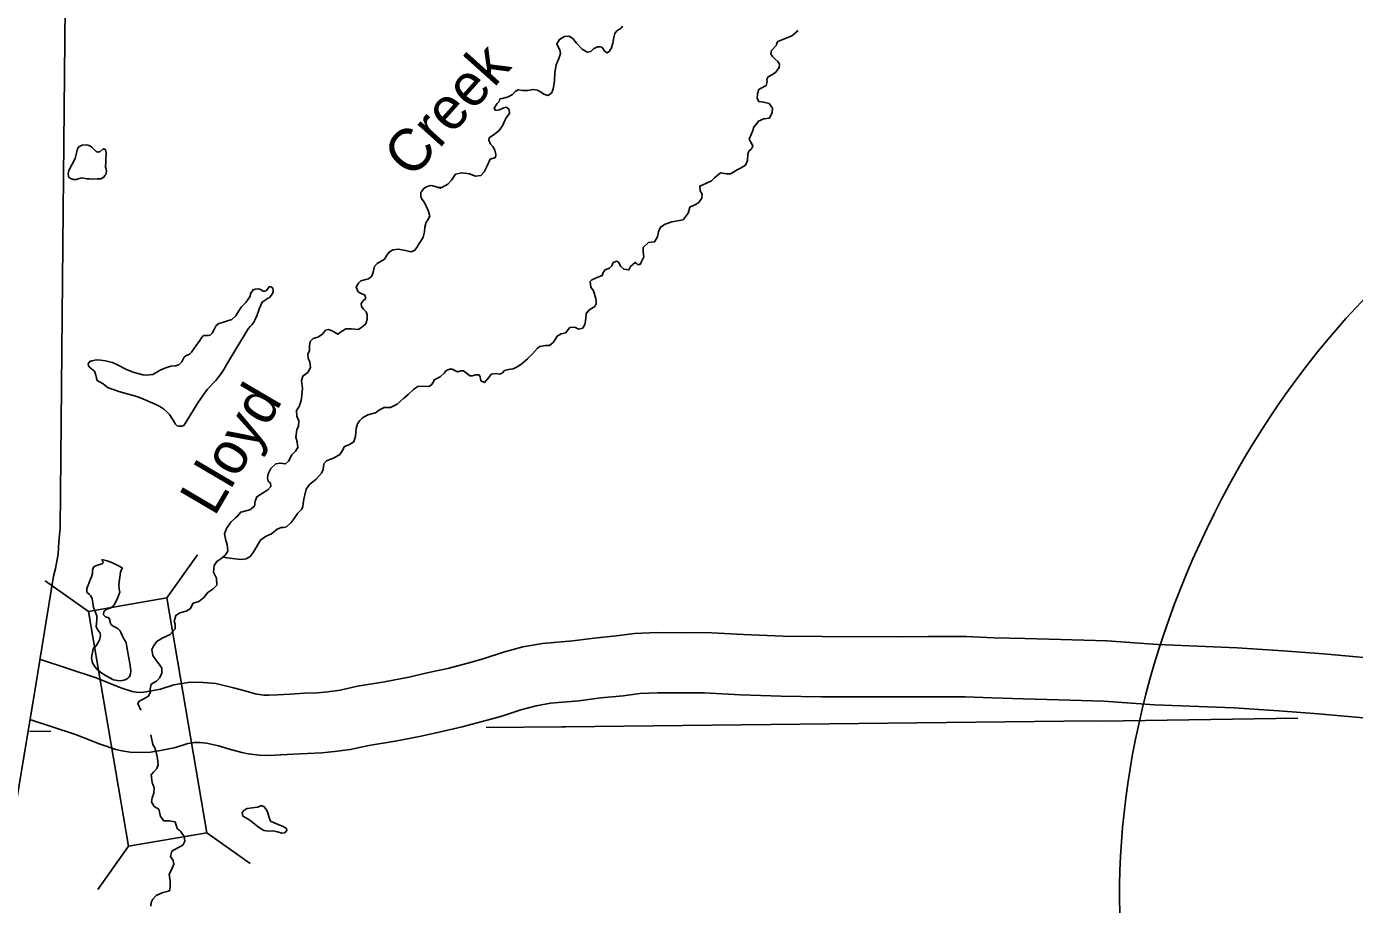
# Model space of a CAD drawing. Extents: x -492261 to -432772, y 1441225 to 1452922.
# Drawn here: x -459788.7 to -459623.3, y 1451872.8 to 1451982.1 of the extents above; entities that cross this region are included whole.
import ezdxf

# ---------------------------------------------------------------- set-up
doc = ezdxf.new("R2010")
doc.units = 0
doc.layers.add('Default', color=7, linetype='Continuous')

msp = doc.modelspace()

# ---------------------------------------------------------------- linework, layer by layer
at = {"layer": 'Default'}
for p, q in [((-459771.2, 1451910.95), (-459767.38, 1451916.33)), ((-459780.96, 1451909.28), (-459786.35, 1451913.1)), ((-459766.22, 1451881.67), (-459760.83, 1451877.85)), ((-459775.98, 1451880.01), (-459779.79, 1451874.62))]:
    msp.add_line(p, q, dxfattribs=at)
for points in [[(-459804.54, 1451796.57), (-459800.12, 1451821.52), (-459795.32, 1451850.99), (-459791.68, 1451875.13), (-459787.55, 1451899.87), (-459785.29, 1451913.65), (-459785.04, 1451914.61), (-459784.72, 1451916.42), (-459784.64, 1451917.99), (-459784.48, 1451919.61), (-459784.15, 1451954.89), (-459783.82, 1451988.91), (-459783.49, 1452028.77), (-459783.44, 1452070.65), (-459782.91, 1452098.16), (-459782.87, 1452118.13)], [(-459714.44, 1451982.2), (-459714.6, 1451981.92), (-459715.13, 1451981.59), (-459715.38, 1451981.28), (-459715.51, 1451980.78), (-459715.64, 1451980.08), (-459715.81, 1451979.5), (-459716.03, 1451979.08), (-459716.35, 1451978.85), (-459716.68, 1451979.07), (-459716.85, 1451979.36), (-459717, 1451979.56), (-459717.22, 1451979.61), (-459717.53, 1451979.59), (-459718.06, 1451979.36), (-459718.36, 1451979.03), (-459718.83, 1451978.93), (-459719.45, 1451979.32), (-459720.14, 1451980.07), (-459720.61, 1451980.63), (-459721.09, 1451980.93), (-459721.65, 1451980.9), (-459722.29, 1451980.53), (-459722.59, 1451979.99), (-459722.45, 1451979.6), (-459722.24, 1451979.24), (-459722.14, 1451978.77), (-459722.38, 1451978.17), (-459722.71, 1451977.37), (-459722.84, 1451976.42), (-459722.91, 1451975.37), (-459723.06, 1451974.33), (-459723.29, 1451973.85), (-459723.72, 1451973.55), (-459724.23, 1451973.7), (-459724.55, 1451973.97), (-459725.01, 1451974.19), (-459725.56, 1451974.31), (-459726.26, 1451974.16), (-459726.9, 1451974.17), (-459727.44, 1451974.23), (-459727.82, 1451974.05), (-459728.13, 1451973.68), (-459728.68, 1451973.36), (-459729.38, 1451973.17), (-459729.69, 1451973.14), (-459729.78, 1451972.81), (-459730.06, 1451972.55), (-459730.41, 1451971.98), (-459730.23, 1451971.69), (-459729.74, 1451971.77), (-459729.22, 1451972.02), (-459728.9, 1451972.08), (-459728.55, 1451971.78), (-459728.49, 1451971.32), (-459728.94, 1451970.75), (-459729.13, 1451970.33), (-459729.36, 1451969.77), (-459729.8, 1451969.18), (-459730.39, 1451968.72), (-459731.02, 1451968.29), (-459731.1, 1451967.98), (-459730.87, 1451967.5), (-459730.6, 1451967.2), (-459730.34, 1451966.72), (-459730.21, 1451966.2), (-459730.26, 1451965.8), (-459730.93, 1451965.6), (-459731.29, 1451964.8), (-459731.66, 1451964.04), (-459732.08, 1451963.57), (-459732.73, 1451963.5), (-459733.5, 1451963.78), (-459734.43, 1451963.89), (-459735.22, 1451963.73), (-459735.72, 1451963.01), (-459736.19, 1451962.5), (-459736.95, 1451962.08), (-459737.49, 1451962.1), (-459737.1, 1451962.01), (-459738.07, 1451962.28), (-459738.33, 1451962.32), (-459738.63, 1451962.26), (-459738.93, 1451962.12), (-459739.2, 1451961.9), (-459739.43, 1451961.63), (-459739.56, 1451961.5), (-459739.56, 1451960.9), (-459739.4, 1451960.59), (-459739.22, 1451960.37), (-459739.01, 1451960.03), (-459738.71, 1451959.39), (-459738.67, 1451959.35), (-459738.45, 1451958.55), (-459738.65, 1451958.1), (-459738.87, 1451957.78), (-459739.04, 1451957.16), (-459739.11, 1451956.54), (-459739.27, 1451955.91)], [(-459692.56, 1451981.65), (-459693.32, 1451980.99), (-459694.46, 1451980.52), (-459695.09, 1451980.28), (-459695.19, 1451980.08), (-459695.26, 1451979.8), (-459695.86, 1451979.16), (-459695.97, 1451978.73), (-459695.75, 1451978.42), (-459695.45, 1451978.13), (-459695.07, 1451977.78), (-459694.89, 1451977.46), (-459694.92, 1451977.02), (-459695.33, 1451976.45), (-459695.75, 1451976.15), (-459696.3, 1451975.88), (-459696.46, 1451975.55), (-459696.41, 1451975.28), (-459696.52, 1451974.79), (-459697.06, 1451974.51), (-459697.44, 1451974.31), (-459697.61, 1451973.76), (-459697.66, 1451973.17), (-459697.46, 1451972.78), (-459696.86, 1451972.73), (-459696.14, 1451972.53), (-459695.76, 1451971.96), (-459695.77, 1451971.41), (-459696.13, 1451970.7), (-459696.84, 1451970.63), (-459697.49, 1451970.36), (-459697.68, 1451970.05), (-459698.06, 1451969.58), (-459698.18, 1451969.19), (-459698.35, 1451968.76), (-459698.66, 1451968.12), (-459698.58, 1451967.92), (-459698.38, 1451967.62), (-459698.18, 1451967.24), (-459698.37, 1451966.89), (-459698.71, 1451966.6), (-459698.81, 1451966.23), (-459698.85, 1451965.46), (-459699.11, 1451964.85), (-459699.73, 1451964.48), (-459700.13, 1451964.27), (-459700.97, 1451963.78), (-459701.46, 1451963.78), (-459702.24, 1451963.89), (-459702.95, 1451963.29), (-459703.33, 1451962.91), (-459704.03, 1451962.57), (-459704.8, 1451962.23), (-459704.77, 1451961.67), (-459704.5, 1451961.27), (-459704.54, 1451960.76), (-459704.97, 1451960.16), (-459705.42, 1451959.94), (-459706.06, 1451959.63), (-459706.27, 1451958.89), (-459706.88, 1451958.05), (-459707.57, 1451957.95), (-459708.29, 1451957.82), (-459709.12, 1451957.51), (-459709.7, 1451957.16), (-459709.94, 1451956.55), (-459710.08, 1451955.95), (-459710.44, 1451955.31), (-459711.2, 1451955.22), (-459711.87, 1451954.6), (-459711.84, 1451954.07), (-459711.78, 1451953.46), (-459712.07, 1451952.85), (-459712.25, 1451952.48), (-459712.57, 1451952.5), (-459712.69, 1451952.62), (-459712.85, 1451952.74), (-459713.43, 1451952.24), (-459713.63, 1451951.81), (-459714.28, 1451951.9), (-459714.68, 1451952.29), (-459714.87, 1451952.73), (-459715.12, 1451952.89), (-459715.58, 1451952.72), (-459715.76, 1451952.31), (-459716.04, 1451952.04), (-459716.6, 1451951.82), (-459716.84, 1451951.49), (-459716.97, 1451951.12), (-459717.5, 1451950.9), (-459718.24, 1451950.6), (-459718.47, 1451950.36), (-459718.36, 1451949.68), (-459718.06, 1451949.2), (-459717.74, 1451948.2), (-459717.7, 1451948.05), (-459717.71, 1451947.57), (-459717.87, 1451947.27), (-459718.63, 1451946.8), (-459718.96, 1451946.33)], [(-459778.87, 1451966.8), (-459778.91, 1451966.84), (-459778.96, 1451966.87), (-459779.04, 1451966.89), (-459779.11, 1451966.89), (-459779.5, 1451966.57), (-459779.75, 1451966.5), (-459780, 1451966.57), (-459780.27, 1451966.84), (-459780.54, 1451967.09), (-459780.7, 1451967.23), (-459781.03, 1451967.37), (-459781.3, 1451967.41), (-459781.74, 1451967.34), (-459782.15, 1451967.13), (-459782.34, 1451966.89), (-459782.45, 1451966.36), (-459782.63, 1451965.69), (-459783.42, 1451964.21), (-459783.48, 1451963.81), (-459783.43, 1451963.43), (-459783.2, 1451963.21), (-459782.82, 1451963.06), (-459782.44, 1451963.08), (-459782.12, 1451963.22), (-459781.8, 1451963.29), (-459781.14, 1451963.18), (-459780.81, 1451963.15), (-459780.42, 1451963.12), (-459779.85, 1451963.15), (-459779.42, 1451963.18), (-459779.06, 1451963.39), (-459778.9, 1451963.58), (-459778.81, 1451963.69), (-459778.75, 1451963.85), (-459778.69, 1451964.1), (-459778.76, 1451964.38), (-459778.82, 1451964.63), (-459778.83, 1451964.79), (-459778.78, 1451965.16), (-459778.79, 1451965.47), (-459778.76, 1451966.37), (-459778.77, 1451966.66), (-459778.82, 1451966.74), (-459778.87, 1451966.8)], [(-459739.27, 1451955.91), (-459739.52, 1451955.48), (-459739.75, 1451955.1), (-459740.04, 1451954.6), (-459740.33, 1451954.25), (-459740.78, 1451954.08), (-459741.47, 1451954.25), (-459742.35, 1451954.41), (-459742.98, 1451954.33), (-459743.47, 1451954.08), (-459743.79, 1451953.67), (-459744.08, 1451953.17), (-459744.56, 1451952.87), (-459745.01, 1451952.62), (-459745.32, 1451952.24), (-459745.5, 1451951.53), (-459745.67, 1451951.02), (-459746.06, 1451950.69), (-459746.39, 1451950.63), (-459747.03, 1451950.44), (-459747.33, 1451950.17), (-459747.61, 1451949.71), (-459747.42, 1451949.14), (-459747.13, 1451948.96), (-459746.52, 1451948.67), (-459746.42, 1451948.24), (-459746.74, 1451947.95), (-459746.97, 1451947.63), (-459746.96, 1451947.24), (-459746.72, 1451946.95), (-459746.38, 1451946.59), (-459746.22, 1451946.21), (-459746.24, 1451945.67), (-459746.39, 1451945.1), (-459746.75, 1451944.8), (-459747.3, 1451944.41), (-459748.19, 1451944.48), (-459748.91, 1451944.49), (-459749.42, 1451944.16), (-459749.87, 1451943.81), (-459750.6, 1451944.21), (-459751.04, 1451944.4), (-459751.41, 1451944.29), (-459751.82, 1451943.82), (-459752.38, 1451943.43), (-459752.95, 1451943.28), (-459753.33, 1451942.9), (-459753.41, 1451942.35), (-459753.4, 1451941.76), (-459753.63, 1451941.33), (-459753.58, 1451940.83), (-459753.39, 1451940.32), (-459753.31, 1451939.66), (-459753.62, 1451939.05), (-459754.26, 1451938.59), (-459754.4, 1451938), (-459754.29, 1451937.07), (-459754.37, 1451936.19), (-459754.47, 1451935.54), (-459754.7, 1451934.8), (-459755.05, 1451934.31), (-459755.01, 1451933.59), (-459754.75, 1451933.01), (-459754.79, 1451932.37), (-459755, 1451931.9), (-459755.13, 1451931), (-459754.94, 1451930.41), (-459754.87, 1451929.68), (-459755.17, 1451929.23), (-459755.62, 1451928.77), (-459756.03, 1451928), (-459756.39, 1451927.65), (-459757.08, 1451927.76), (-459757.62, 1451927.66), (-459758.24, 1451927.06), (-459758.55, 1451926.4), (-459758.67, 1451925.87), (-459758.58, 1451925.51), (-459758.28, 1451925.24), (-459758.22, 1451924.82), (-459758.61, 1451924.42), (-459759.41, 1451923.94), (-459759.98, 1451923.55), (-459760.17, 1451923.01), (-459760.28, 1451922.4), (-459760.85, 1451921.94), (-459761.98, 1451921.64), (-459762.49, 1451921.04), (-459762.63, 1451920.93), (-459763.23, 1451920.4), (-459763.78, 1451919.59), (-459763.99, 1451918.92), (-459763.84, 1451918.09), (-459763.69, 1451917.62), (-459763.59, 1451916.78), (-459763.9, 1451916.31), (-459764.45, 1451915.84), (-459764.98, 1451915.51), (-459765.3, 1451915), (-459765.37, 1451914.18), (-459764.99, 1451913.41)], [(-459777.17, 1451936.68), (-459774.81, 1451936), (-459774.11, 1451935.7), (-459772.65, 1451935.09), (-459772.08, 1451934.79), (-459771.58, 1451934.46), (-459771.2, 1451934.13), (-459770.86, 1451933.79), (-459770.41, 1451933.1), (-459770.25, 1451932.82), (-459770.11, 1451932.59), (-459769.9, 1451932.41), (-459769.72, 1451932.34), (-459769.52, 1451932.33), (-459769.31, 1451932.36), (-459769.09, 1451932.45), (-459768.89, 1451932.67), (-459767.25, 1451935.4), (-459766.16, 1451936.9), (-459765.08, 1451938.06), (-459764.37, 1451938.94), (-459764.09, 1451939.41), (-459763.73, 1451940.07), (-459762.49, 1451942.15), (-459761.7, 1451943.45), (-459761.05, 1451944.47), (-459760.75, 1451944.8), (-459760.56, 1451945.03), (-459760.33, 1451945.38), (-459760.19, 1451945.64), (-459759.97, 1451946.09), (-459759.69, 1451946.92), (-459759.5, 1451947.41), (-459759.31, 1451947.8), (-459759.06, 1451947.98), (-459758.82, 1451948.13), (-459758.56, 1451948.28), (-459758.41, 1451948.4), (-459758.14, 1451948.67), (-459758.05, 1451948.82), (-459757.96, 1451949.06), (-459757.93, 1451949.3), (-459757.99, 1451949.49), (-459758.07, 1451949.62), (-459758.24, 1451949.72), (-459758.41, 1451949.73), (-459758.52, 1451949.58), (-459758.68, 1451949.36), (-459758.79, 1451949.25), (-459758.99, 1451949.15), (-459759.18, 1451949.16), (-459759.51, 1451949.36), (-459759.79, 1451949.47), (-459760.2, 1451949.43), (-459760.42, 1451949.35), (-459760.71, 1451948.91), (-459760.86, 1451948.46), (-459761.35, 1451947.75), (-459761.88, 1451947.2), (-459762.23, 1451946.72), (-459762.59, 1451946.11), (-459763.11, 1451945.62), (-459763.74, 1451945.43), (-459764.12, 1451945.32), (-459764.71, 1451945.12), (-459765.04, 1451944.88), (-459765.31, 1451944.41), (-459765.53, 1451943.93), (-459765.78, 1451943.69), (-459766.01, 1451943.64), (-459766.46, 1451943.66), (-459766.62, 1451943.65), (-459766.9, 1451943.31), (-459767.09, 1451943.04), (-459767.52, 1451942.41), (-459768.11, 1451941.57), (-459768.38, 1451941.3), (-459768.81, 1451941.13), (-459769.04, 1451940.93), (-459769.34, 1451940.36), (-459769.69, 1451940), (-459770.17, 1451939.86), (-459770.7, 1451939.81), (-459771.46, 1451939.57), (-459772.03, 1451939.32), (-459772.93, 1451938.79), (-459773.75, 1451938.7), (-459774.2, 1451938.75), (-459775.27, 1451939.04), (-459775.73, 1451939.21)], [(-459718.96, 1451946.33), (-459719.04, 1451945.45), (-459719.11, 1451945), (-459719.39, 1451944.55), (-459719.9, 1451944.44), (-459720.38, 1451944.69), (-459720.98, 1451944.65), (-459721.32, 1451944.21), (-459721.5, 1451943.97), (-459722.07, 1451943.86), (-459722.57, 1451943.56), (-459722.73, 1451943.26), (-459723.07, 1451942.78), (-459723.53, 1451942.4), (-459724.03, 1451942.39), (-459724.72, 1451942.26), (-459725.01, 1451942.05), (-459725.66, 1451941.35), (-459726.28, 1451940.72), (-459726.92, 1451940.14), (-459727.46, 1451939.77), (-459728.06, 1451939.49), (-459728.63, 1451939.39), (-459729.13, 1451939.28), (-459729.36, 1451939.01), (-459729.72, 1451938.84), (-459730.23, 1451938.91), (-459730.79, 1451938.84), (-459731.09, 1451938.4), (-459731.64, 1451937.79), (-459732.06, 1451938), (-459732.15, 1451938.49), (-459732.29, 1451938.76), (-459732.72, 1451938.76), (-459733.14, 1451938.61), (-459733.46, 1451938.64), (-459733.92, 1451938.98), (-459734.24, 1451939.24), (-459734.58, 1451939.23), (-459734.98, 1451939.1), (-459735.42, 1451939.33), (-459735.66, 1451939.47), (-459736, 1451939.45), (-459736.42, 1451939.23), (-459736.61, 1451938.98), (-459737.15, 1451938.51), (-459737.87, 1451938.11), (-459737.99, 1451937.88), (-459738.21, 1451937.48), (-459738.57, 1451937.3), (-459739.32, 1451937.33), (-459739.94, 1451937.29), (-459740.44, 1451936.98), (-459741.12, 1451936.3), (-459741.66, 1451935.83), (-459742.48, 1451935.11), (-459743.31, 1451934.67), (-459744.11, 1451934.67), (-459744.7, 1451934.4), (-459745.19, 1451934), (-459746.14, 1451933.75), (-459746.83, 1451933.39), (-459747.16, 1451933.05), (-459747.46, 1451932.64), (-459747.61, 1451932.08), (-459747.67, 1451931.1), (-459747.91, 1451930.41), (-459748.53, 1451930.03), (-459749.07, 1451929.83), (-459749.41, 1451929.2), (-459749.63, 1451928.8), (-459750.33, 1451928.39), (-459751.29, 1451928.03), (-459751.64, 1451927.64), (-459751.71, 1451926.94), (-459751.91, 1451926.48), (-459752.58, 1451925.74), (-459753.41, 1451925.09), (-459753.82, 1451924.5), (-459754.02, 1451923.79), (-459754.06, 1451923.65), (-459754.13, 1451923.25), (-459754.21, 1451922.68), (-459754.24, 1451922.33), (-459754.38, 1451922), (-459754.91, 1451921.49), (-459755.33, 1451920.85), (-459755.71, 1451920.33), (-459756.27, 1451919.81), (-459756.65, 1451919.73), (-459756.95, 1451919.72), (-459757.46, 1451919.51), (-459758.16, 1451918.95), (-459758.92, 1451918.6), (-459759.53, 1451918.16), (-459759.89, 1451917.53), (-459760.24, 1451916.94), (-459760.53, 1451916.49), (-459760.83, 1451916.1), (-459761.3, 1451915.81), (-459761.98, 1451915.72)], [(-459775.73, 1451939.21), (-459776.22, 1451939.39), (-459777.43, 1451940.05), (-459777.96, 1451940.27), (-459778.34, 1451940.38), (-459778.85, 1451940.48), (-459779.46, 1451940.57), (-459779.94, 1451940.61), (-459780.54, 1451940.51), (-459780.79, 1451940.39), (-459781, 1451940.12), (-459780.93, 1451939.85), (-459780.73, 1451939.6), (-459780.22, 1451939.19), (-459780.05, 1451938.72), (-459779.96, 1451938.32), (-459779.88, 1451938.02), (-459779.59, 1451937.87), (-459779.12, 1451937.62), (-459778.93, 1451937.45), (-459778.59, 1451937.18), (-459777.17, 1451936.68)], [(-459761.98, 1451915.72), (-459763.34, 1451915.92), (-459764.2, 1451916.05)], [(-459779.29, 1451915.73), (-459779.16, 1451915.5), (-459779.14, 1451915.34), (-459779.26, 1451915.21), (-459779.72, 1451915.08), (-459780.02, 1451914.95), (-459780.32, 1451914.8), (-459780.47, 1451914.4), (-459780.45, 1451914.05), (-459780.57, 1451913.59), (-459780.75, 1451913.19), (-459781, 1451912.56), (-459781.17, 1451912.12), (-459781.14, 1451911.65), (-459780.82, 1451911.36), (-459780.66, 1451911.2), (-459780.49, 1451910.82), (-459780.4, 1451910.33), (-459780.34, 1451909.75), (-459780.14, 1451909.27), (-459779.9, 1451908.71), (-459779.92, 1451908.17), (-459780.01, 1451907.39), (-459779.79, 1451906.92), (-459779.54, 1451906.64), (-459779.44, 1451906.3), (-459779.52, 1451905.82), (-459779.76, 1451905.38), (-459780.04, 1451904.96), (-459780.36, 1451904.65), (-459780.58, 1451903.5), (-459780.45, 1451902.88), (-459780.21, 1451902.44), (-459779.87, 1451902.04), (-459779.43, 1451901.65), (-459778.82, 1451901.27), (-459777.83, 1451900.76), (-459777.34, 1451900.66), (-459776.93, 1451900.63), (-459776.53, 1451900.69), (-459776.31, 1451900.78), (-459776.11, 1451900.93), (-459775.96, 1451901.02), (-459775.85, 1451901.13), (-459775.71, 1451901.5), (-459775.66, 1451901.84), (-459775.76, 1451902.52), (-459776.18, 1451904.85), (-459776.25, 1451905.35), (-459776.37, 1451905.62), (-459776.57, 1451905.93), (-459776.71, 1451906.17), (-459776.91, 1451906.65), (-459777.04, 1451906.9), (-459777.26, 1451907.12), (-459777.56, 1451907.28), (-459777.89, 1451907.43), (-459778.12, 1451907.64), (-459778.26, 1451907.91), (-459778.28, 1451908.19), (-459778.38, 1451908.42), (-459778.54, 1451908.52), (-459778.83, 1451908.6), (-459779.1, 1451908.86), (-459779.06, 1451909.25), (-459778.96, 1451909.36), (-459778.75, 1451909.5), (-459778.56, 1451909.6), (-459778.27, 1451909.69), (-459777.91, 1451909.88), (-459777.76, 1451910.11), (-459777.48, 1451910.64), (-459777.28, 1451911.01), (-459777.16, 1451911.34), (-459777.05, 1451911.69), (-459777.12, 1451912.04), (-459777.18, 1451912.64), (-459776.95, 1451914.15), (-459776.82, 1451914.48), (-459776.73, 1451914.66)], [(-459779.29, 1451915.73), (-459778.61, 1451915.56), (-459777.94, 1451915.32), (-459777.13, 1451914.9), (-459776.73, 1451914.66)], [(-459764.99, 1451913.41), (-459764.98, 1451912.56), (-459765.48, 1451912.06), (-459766.09, 1451911.61), (-459766.58, 1451911.01), (-459767.19, 1451910.51), (-459767.9, 1451910.3), (-459768.28, 1451909.61), (-459768.79, 1451909.3), (-459769.57, 1451909.11), (-459770.05, 1451908.77), (-459770.28, 1451908.03), (-459770.17, 1451907.67), (-459770.15, 1451907.1), (-459770.78, 1451906.39), (-459771.78, 1451905.96), (-459772.43, 1451905.51), (-459772.82, 1451905.02), (-459773.08, 1451904.51), (-459772.94, 1451903.79), (-459772.47, 1451903.12), (-459772.16, 1451902.69), (-459771.8, 1451902.21), (-459771.82, 1451901.56), (-459772.12, 1451900.94), (-459772.49, 1451900.59), (-459773.15, 1451900.2), (-459773.28, 1451899.6), (-459773.21, 1451899.24), (-459773.49, 1451898.72), (-459774.16, 1451898.34), (-459774.65, 1451898.09), (-459774.79, 1451897.82), (-459774.42, 1451896.97)], [(-459786.93, 1451903.29), (-459780.01, 1451901), (-459776.93, 1451899.77), (-459775.49, 1451899.3), (-459775.28, 1451899.25), (-459774.99, 1451899.2), (-459774.42, 1451899.18), (-459774.06, 1451899.2), (-459773.36, 1451899.32), (-459771.97, 1451899.6), (-459770.34, 1451900.11), (-459768.3, 1451900.46), (-459766.66, 1451900.42), (-459765.07, 1451900.28), (-459762.88, 1451899.77), (-459761.31, 1451899.32), (-459760.18, 1451899), (-459759.94, 1451898.95), (-459759.1, 1451898.85), (-459758.5, 1451898.83), (-459757.39, 1451898.89), (-459755.82, 1451898.96), (-459754.05, 1451899.07), (-459752.44, 1451899.14), (-459751.12, 1451899.27), (-459749.61, 1451899.45), (-459747.46, 1451899.94), (-459744.06, 1451900.5), (-459741.06, 1451901.08), (-459738.38, 1451901.69), (-459736.18, 1451902.18), (-459733.24, 1451902.96), (-459731.66, 1451903.4), (-459729.26, 1451904.2), (-459726.85, 1451904.85), (-459724.4, 1451905.29), (-459720.63, 1451905.61), (-459717.94, 1451905.95), (-459715.21, 1451906.21), (-459712.92, 1451906.51), (-459710.17, 1451906.64), (-459706.57, 1451906.62), (-459704.11, 1451906.65), (-459699.36, 1451906.39), (-459694.44, 1451906.2), (-459689.57, 1451906.13), (-459680.15, 1451906.12), (-459676.31, 1451906.13), (-459671.61, 1451906.15), (-459668.12, 1451906), (-459664.33, 1451905.89), (-459659.84, 1451905.76), (-459654.09, 1451905.59), (-459647.75, 1451905.14), (-459637.85, 1451904.74), (-459632.16, 1451904.37), (-459627.12, 1451904), (-459621.64, 1451903.51)], [(-459788.24, 1451895.82), (-459782.58, 1451893.95), (-459779.48, 1451892.72), (-459777.56, 1451892.09), (-459776.81, 1451891.91), (-459775.75, 1451891.73), (-459774.37, 1451891.68), (-459773.24, 1451891.73), (-459772, 1451891.94), (-459770.11, 1451892.32), (-459768.56, 1451892.81), (-459767.76, 1451892.95), (-459767.09, 1451892.93), (-459766.24, 1451892.85), (-459764.77, 1451892.51), (-459763.38, 1451892.11), (-459761.86, 1451891.68), (-459761.04, 1451891.53), (-459759.69, 1451891.37), (-459758.44, 1451891.32), (-459757.01, 1451891.4), (-459755.43, 1451891.47), (-459753.66, 1451891.58), (-459751.89, 1451891.66), (-459750.31, 1451891.82), (-459748.34, 1451892.05), (-459746.01, 1451892.58), (-459742.74, 1451893.12), (-459739.52, 1451893.74), (-459736.73, 1451894.37), (-459734.4, 1451894.9), (-459731.27, 1451895.72), (-459729.47, 1451896.23), (-459727.1, 1451897.01), (-459725.2, 1451897.53), (-459723.41, 1451897.85), (-459719.85, 1451898.15), (-459717.11, 1451898.49), (-459714.36, 1451898.76), (-459712.27, 1451899.03), (-459710.02, 1451899.14), (-459706.54, 1451899.12), (-459704.26, 1451899.15), (-459699.72, 1451898.9), (-459694.65, 1451898.7), (-459689.63, 1451898.63), (-459680.14, 1451898.62), (-459676.29, 1451898.63), (-459671.76, 1451898.65), (-459668.4, 1451898.51), (-459664.55, 1451898.39), (-459660.06, 1451898.26), (-459654.47, 1451898.1), (-459648.17, 1451897.65), (-459638.24, 1451897.25), (-459632.68, 1451896.89), (-459627.73, 1451896.52), (-459622.17, 1451896.03)], [(-459731.42, 1451894.83), (-459721.98, 1451894.91), (-459721.53, 1451894.9), (-459655.78, 1451895.66), (-459654.71, 1451895.6), (-459630.31, 1451895.98)], [(-459788.31, 1451894.33), (-459785.66, 1451894.35)], [(-459773.18, 1451893.9), (-459772.94, 1451892.7), (-459772.68, 1451892.26), (-459772.46, 1451891.57), (-459772.36, 1451890.93), (-459772.29, 1451890.17), (-459772.43, 1451889.7), (-459772.84, 1451889.24), (-459773.16, 1451888.92), (-459773, 1451887.97), (-459772.77, 1451887.31), (-459772.81, 1451886.61), (-459773.03, 1451886.06), (-459773.12, 1451885.53), (-459772.75, 1451884.97), (-459772.18, 1451884.62), (-459771.98, 1451883.73), (-459771.58, 1451883.18), (-459770.92, 1451883.17), (-459770.17, 1451883.05), (-459769.91, 1451882.24), (-459769.5, 1451881.9), (-459769.02, 1451881.23), (-459768.95, 1451880.66), (-459769.2, 1451880.16), (-459769.81, 1451879.82), (-459770.55, 1451879.4), (-459770.72, 1451878.72), (-459770.4, 1451878.26), (-459770.3, 1451877.77), (-459770.63, 1451877.06), (-459770.91, 1451876.54), (-459770.76, 1451875.67), (-459770.76, 1451875.14), (-459770.83, 1451874.52), (-459771.15, 1451874.37), (-459771.71, 1451874.25), (-459772.53, 1451873.88), (-459772.94, 1451873.44), (-459773.13, 1451873), (-459773.17, 1451872.55)], [(-459758.79, 1451884.57), (-459758.9, 1451884.74), (-459759.06, 1451884.93), (-459759.41, 1451885.09), (-459759.57, 1451885), (-459759.88, 1451884.88), (-459761.18, 1451884.74), (-459761.55, 1451884.53), (-459761.81, 1451884.21), (-459761.74, 1451883.78), (-459761.2, 1451883.48), (-459760.7, 1451883.15), (-459759.79, 1451882.39), (-459759.11, 1451881.97), (-459758.55, 1451881.91), (-459758, 1451881.94), (-459757.41, 1451881.83), (-459756.88, 1451881.66), (-459756.51, 1451881.69), (-459756.26, 1451881.97), (-459756.3, 1451882.22), (-459756.68, 1451882.46), (-459757.31, 1451882.71), (-459757.82, 1451882.92), (-459758.26, 1451883.16), (-459758.5, 1451883.71), (-459758.62, 1451884.16), (-459758.79, 1451884.57)]]:
    msp.add_lwpolyline(points, dxfattribs=at)
msp.add_lwpolyline([(-459766.22, 1451881.67), (-459771.2, 1451910.95), (-459780.96, 1451909.28), (-459775.98, 1451880.01)], close=True, dxfattribs=at)
msp.add_ellipse((-459592.08, 1451895.81), major_axis=(-34.55, -72.06), ratio=0.687937, dxfattribs=at)

# ---------------------------------------------------------------- texts
for s, rotation, p in [('Creek', 48.1299, (-459740.68, 1451963.04)), ('Lloyd', 59.5317, (-459765.27, 1451920.98))]:
    msp.add_text(s, height=5.28, rotation=rotation, dxfattribs=at).set_placement(p)

doc.saveas('drawing.dxf')
